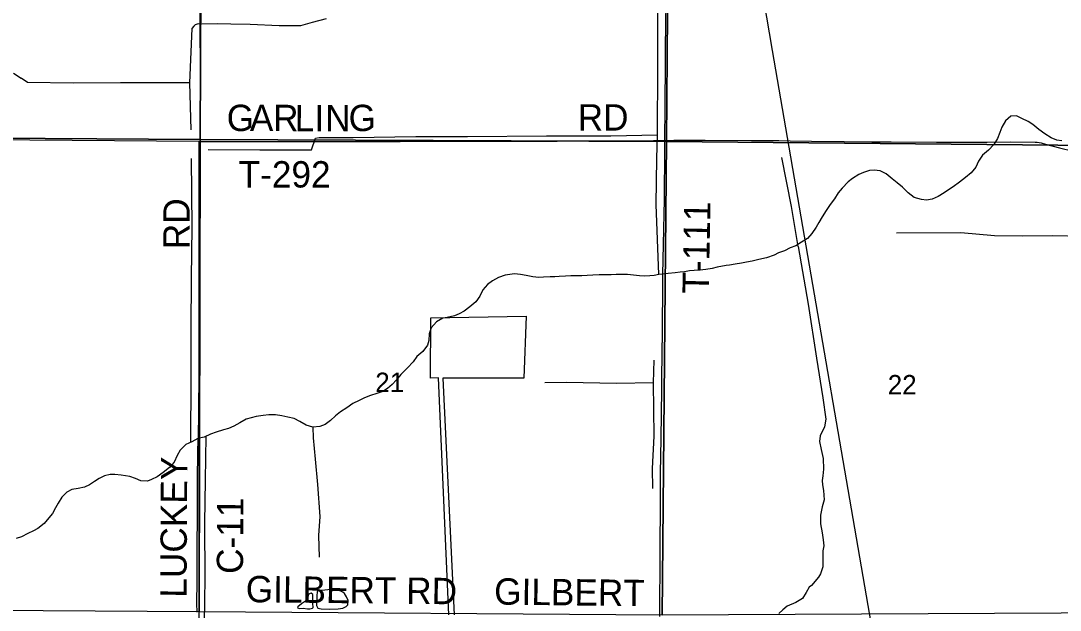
# Model space of a CAD drawing. Extents: x 1443599 to 1910620, y 1028088 to 1361369.
# Drawn here: x 1694297 to 1706140, y 1260936 to 1267645 of the extents above; entities that cross this region are included whole.
import ezdxf

# ---------------------------------------------------------------- set-up
doc = ezdxf.new("R2010")
doc.units = 0
for name, color, linetype in [('GM_X_Corporation', 7, 'Continuous'), ('GM_X_County_Road', 7, 'Continuous'), ('GM_X_County_Road_Text', 7, 'Continuous'), ('GM_X_Major_River', 7, 'Continuous'), ('GM_X_Minor_Lake', 7, 'Continuous'), ('GM_X_Minor_River', 7, 'Continuous'), ('GM_X_Rail_Line', 7, 'Continuous'), ('GM_X_Section', 7, 'Continuous'), ('GM_X_Section_Text', 7, 'Continuous'), ('GM_X_Township', 7, 'Continuous'), ('GM_X_Township_Road', 7, 'Continuous'), ('GM_X_Township_Road_Text', 7, 'Continuous')]:
    doc.layers.add(name, color=color, linetype=linetype)

msp = doc.modelspace()

# ---------------------------------------------------------------- linework, layer by layer
at = {"layer": 'GM_X_Corporation'}
msp.add_lwpolyline([(1699175, 1260884), (1699056, 1263580), (1698965, 1263578), (1698970, 1264262), (1700055, 1264281), (1700027, 1263577), (1699104, 1263575), (1699233, 1260884)], dxfattribs=at)
at = {"layer": 'GM_X_County_Road'}
for points in [[(1696343, 1266271), (1696343, 1266398), (1696343, 1266447), (1696343, 1266811), (1696343, 1267038), (1696343, 1267245), (1696342, 1267422), (1696341, 1267563), (1696340, 1267668), (1696339, 1267859), (1696339, 1268052), (1696337, 1268305), (1696338, 1268413), (1696337, 1268627), (1696337, 1268721), (1696336, 1268836), (1696337, 1268931)], [(1696305, 1260914), (1696304, 1261011), (1696305, 1261267), (1696306, 1261441), (1696307, 1261733), (1696310, 1261933), (1696311, 1262317), (1696311, 1262541), (1696313, 1262615), (1696315, 1262763), (1696321, 1262940), (1696325, 1263153), (1696327, 1263304), (1696329, 1263524), (1696329, 1263725), (1696331, 1263994), (1696331, 1264053), (1696331, 1264204), (1696331, 1264270), (1696335, 1264544), (1696335, 1264675), (1696336, 1264840), (1696336, 1264997), (1696338, 1265155), (1696338, 1265256), (1696338, 1265450), (1696339, 1265578), (1696339, 1265680), (1696341, 1266159), (1696343, 1266266), (1696343, 1266271)]]:
    msp.add_lwpolyline(points, dxfattribs=at)
at = {"layer": 'GM_X_Major_River'}
for points in [[(1705829, 1266464), (1705776, 1266497), (1705701, 1266533), (1705641, 1266562), (1705579, 1266560), (1705518, 1266507), (1705474, 1266434), (1705451, 1266372), (1705427, 1266303), (1705383, 1266238), (1705324, 1266173), (1705256, 1266115), (1705209, 1266046), (1705177, 1265980), (1705127, 1265915), (1705060, 1265861), (1704991, 1265808), (1704922, 1265754), (1704869, 1265721), (1704818, 1265688), (1704749, 1265644), (1704682, 1265616), (1704618, 1265603), (1704558, 1265611), (1704477, 1265633), (1704408, 1265688), (1704342, 1265750), (1704281, 1265802), (1704226, 1265847), (1704157, 1265901), (1704090, 1265936), (1704019, 1265946), (1703966, 1265941), (1703900, 1265919), (1703847, 1265894), (1703774, 1265850), (1703723, 1265811), (1703655, 1265741), (1703610, 1265686), (1703569, 1265620), (1703517, 1265552), (1703473, 1265487), (1703429, 1265415), (1703390, 1265348), (1703361, 1265297), (1703309, 1265224), (1703259, 1265165), (1703194, 1265123), (1703127, 1265084), (1703065, 1265060), (1702998, 1265027), (1702931, 1265005), (1702879, 1264978), (1702794, 1264948), (1702740, 1264936), (1702691, 1264922), (1702629, 1264910), (1702565, 1264897), (1702510, 1264885), (1702438, 1264874), (1702370, 1264864), (1702335, 1264858), (1702231, 1264839), (1702173, 1264827), (1702101, 1264814), (1702035, 1264806), (1701969, 1264802), (1701916, 1264797), (1701858, 1264788), (1701808, 1264783), (1701752, 1264777), (1701674, 1264767), (1701616, 1264760), (1701566, 1264757), (1701515, 1264744), (1701463, 1264742), (1701409, 1264739), (1701347, 1264742), (1701279, 1264750), (1701208, 1264756), (1701148, 1264757), (1701082, 1264755), (1701024, 1264752), (1700956, 1264752), (1700888, 1264754), (1700815, 1264749), (1700749, 1264745), (1700691, 1264740), (1700623, 1264742), (1700565, 1264741), (1700503, 1264737), (1700433, 1264733), (1700381, 1264732), (1700329, 1264729), (1700253, 1264725), (1700201, 1264722), (1700131, 1264732), (1700054, 1264744), (1699992, 1264755), (1699922, 1264763), (1699868, 1264756)], [(1706158, 1266279), (1706102, 1266285), (1706035, 1266314), (1705966, 1266358), (1705897, 1266406), (1705829, 1266464)], [(1699868, 1264756), (1699816, 1264751), (1699741, 1264723), (1699672, 1264683), (1699615, 1264642), (1699562, 1264583), (1699526, 1264512), (1699482, 1264445), (1699413, 1264390), (1699348, 1264340), (1699291, 1264311), (1699240, 1264286), (1699156, 1264266), (1699104, 1264258), (1699035, 1264217), (1698971, 1264151), (1698951, 1264081), (1698947, 1264007), (1698930, 1263954), (1698878, 1263882), (1698811, 1263822), (1698767, 1263763), (1698704, 1263694), (1698628, 1263620), (1698576, 1263557), (1698529, 1263504), (1698476, 1263459), (1698421, 1263425), (1698353, 1263402), (1698282, 1263378), (1698215, 1263353), (1698151, 1263323), (1698082, 1263287), (1698013, 1263240), (1697939, 1263192), (1697882, 1263147), (1697827, 1263094), (1697766, 1263048), (1697704, 1263026), (1697625, 1263021), (1697550, 1263043), (1697477, 1263083), (1697410, 1263116), (1697340, 1263134), (1697270, 1263148), (1697199, 1263158), (1697125, 1263159), (1697059, 1263151), (1696980, 1263139), (1696864, 1263110), (1696791, 1263067), (1696726, 1263031), (1696665, 1263004), (1696607, 1262990), (1696522, 1262962), (1696458, 1262941), (1696387, 1262907), (1696316, 1262890), (1696245, 1262854), (1696177, 1262820), (1696113, 1262759), (1696080, 1262698), (1696044, 1262622), (1695990, 1262560), (1695919, 1262503), (1695852, 1262455), (1695785, 1262424), (1695739, 1262404), (1695664, 1262407), (1695603, 1262433), (1695538, 1262458), (1695442, 1262473), (1695368, 1262480), (1695314, 1262480), (1695252, 1262465), (1695191, 1262433), (1695138, 1262402), (1695079, 1262361), (1695023, 1262337), (1694950, 1262322), (1694878, 1262310), (1694821, 1262279), (1694766, 1262221), (1694724, 1262155), (1694693, 1262102), (1694657, 1262037), (1694618, 1261986), (1694563, 1261921), (1694493, 1261866), (1694443, 1261838), (1694376, 1261807), (1694305, 1261769), (1694243, 1261750)]]:
    msp.add_lwpolyline(points, dxfattribs=at)
at = {"layer": 'GM_X_Minor_Lake'}
for p, q in [((1697625, 1261011), (1697626, 1261099)), ((1697670, 1261106), (1697667, 1260988))]:
    msp.add_line(p, q, dxfattribs=at)
for points in [[(1697667, 1260988), (1697680, 1260960), (1697718, 1260953), (1697818, 1260946), (1697912, 1260952), (1697966, 1260957), (1698004, 1260978), (1698023, 1260998), (1698028, 1261048), (1698009, 1261088), (1697986, 1261125), (1697967, 1261141), (1697909, 1261167), (1697829, 1261171), (1697763, 1261164), (1697717, 1261161), (1697677, 1261166), (1697670, 1261106)], [(1697626, 1261099), (1697624, 1261115), (1697604, 1261128), (1697576, 1261119), (1697565, 1261069), (1697540, 1261037), (1697495, 1261008), (1697454, 1260973), (1697448, 1260961), (1697468, 1260955), (1697514, 1260958), (1697562, 1260953), (1697592, 1260950), (1697622, 1260957), (1697630, 1260967), (1697625, 1261011)]]:
    msp.add_lwpolyline(points, dxfattribs=at)
at = {"layer": 'GM_X_Minor_River'}
for points in [[(1701566, 1264757), (1701537, 1265553), (1701545, 1266077), (1701551, 1266345), (1701554, 1267128), (1701557, 1267968)], [(1697777, 1267666), (1697616, 1267624), (1697483, 1267587), (1697241, 1267587), (1696909, 1267601), (1696689, 1267608), (1696543, 1267610), (1696359, 1267606), (1696317, 1267609), (1696285, 1267600), (1696267, 1267585), (1696246, 1267557), (1696221, 1266938), (1696235, 1266403)], [(1694214, 1267050), (1694300, 1266991)], [(1696221, 1266938), (1695433, 1266940), (1694893, 1266935), (1694373, 1266941), (1694300, 1266991)], [(1696432, 1266178), (1697020, 1266174), (1697608, 1266174), (1697655, 1266309), (1697697, 1266318), (1698085, 1266318), (1698799, 1266327), (1699387, 1266329), (1700287, 1266335), (1701021, 1266335), (1701551, 1266345)], [(1696233, 1262848), (1696237, 1263564), (1696237, 1264133), (1696242, 1264716), (1696248, 1265295), (1696241, 1266076)], [(1703153, 1265077), (1703078, 1265530), (1702970, 1266088)], [(1706393, 1265189), (1706055, 1265198), (1705709, 1265192), (1705392, 1265198), (1705009, 1265231), (1704275, 1265229)], [(1703153, 1265077), (1703267, 1264419), (1703362, 1263806), (1703434, 1263353), (1703468, 1263110), (1703454, 1263024), (1703405, 1262919), (1703398, 1262855), (1703416, 1262765), (1703439, 1262664), (1703442, 1262542), (1703434, 1262464), (1703429, 1262412), (1703430, 1262364), (1703444, 1262297), (1703451, 1262191), (1703427, 1262113), (1703409, 1262019), (1703409, 1261919), (1703426, 1261815), (1703440, 1261738), (1703448, 1261670), (1703435, 1261612), (1703435, 1261528), (1703434, 1261428), (1703407, 1261350), (1703386, 1261313), (1703305, 1261218), (1703279, 1261199), (1703245, 1261136), (1703204, 1261067), (1703128, 1261022), (1703029, 1260983), (1702978, 1260940), (1702935, 1260897)], [(1701509, 1263783), (1701503, 1263524), (1701508, 1262915), (1701489, 1262549), (1701493, 1262320)], [(1701503, 1263524), (1701087, 1263518), (1700511, 1263528), (1700269, 1263522)], [(1697625, 1263021), (1697628, 1262899), (1697650, 1262656), (1697677, 1262367), (1697704, 1262001), (1697689, 1261785), (1697695, 1261541)], [(1696405, 1262915), (1696396, 1262414), (1696392, 1261925), (1696393, 1261302), (1696388, 1260785), (1696388, 1259965), (1696359, 1259944), (1696369, 1259635), (1696390, 1259085), (1696387, 1258657), (1696362, 1258287), (1696373, 1258022), (1696362, 1257657), (1696353, 1257133)]]:
    msp.add_lwpolyline(points, dxfattribs=at)
at = {"layer": 'GM_X_Rail_Line'}
msp.add_lwpolyline([(1706691, 1244888), (1706606, 1245603), (1706377, 1246883), (1705814, 1250181), (1704887, 1255544), (1704203, 1259536), (1702861, 1267305), (1702177, 1271327), (1700946, 1278383), (1700946, 1278377), (1700041, 1283682), (1699417, 1287303)], dxfattribs=at)
at = {"layer": 'GM_X_Section'}
for points in [[(1691085, 1271702), (1696362, 1271606), (1696341, 1266293), (1691034, 1266328)], [(1701697, 1271615), (1701654, 1266271), (1696341, 1266293), (1696362, 1271606)], [(1706954, 1271617), (1706926, 1266222), (1701654, 1266271), (1701697, 1271615)], [(1696341, 1266293), (1696328, 1260919), (1690993, 1260950), (1691034, 1266328)], [(1701654, 1266271), (1701604, 1260880), (1696328, 1260919), (1696341, 1266293)], [(1706926, 1266222), (1706905, 1260906), (1701604, 1260880), (1701654, 1266271)]]:
    msp.add_lwpolyline(points, close=True, dxfattribs=at)
at = {"layer": 'GM_X_Township'}
for points in [[(1691028, 1266317), (1696325, 1266276), (1696324, 1260894), (1696308, 1259201), (1696305, 1258547), (1696301, 1258173), (1696288, 1257097), (1696269, 1255587), (1696154, 1250250)], [(1691028, 1266317), (1696325, 1266276), (1696324, 1260894), (1696308, 1259201), (1696305, 1258547), (1696301, 1258173), (1696288, 1257097), (1696269, 1255587), (1696154, 1250250), (1695980, 1244960), (1695885, 1241542), (1695846, 1239693), (1695686, 1234412), (1693554, 1234401)]]:
    msp.add_lwpolyline(points, dxfattribs=at)
at = {"layer": 'GM_X_Township_Road'}
for points in [[(1701635, 1266284), (1701636, 1266405), (1701639, 1266546), (1701640, 1266839), (1701642, 1267003), (1701643, 1267226), (1701644, 1267393), (1701646, 1267541), (1701646, 1267646), (1701650, 1267820), (1701652, 1268102), (1701653, 1268326), (1701653, 1268696), (1701654, 1268946), (1701654, 1268962)], [(1696343, 1266271), (1696387, 1266271), (1696754, 1266270), (1697125, 1266271)], [(1697125, 1266271), (1697208, 1266271), (1697462, 1266272), (1697800, 1266271), (1698184, 1266270), (1698358, 1266270), (1698621, 1266272), (1699921, 1266275), (1700193, 1266276), (1700407, 1266276), (1700646, 1266277), (1700942, 1266277), (1701165, 1266279), (1701356, 1266280), (1701507, 1266281), (1701635, 1266284)], [(1701580, 1260863), (1701579, 1261153), (1701581, 1261313), (1701582, 1261454), (1701582, 1261635), (1701583, 1261776), (1701585, 1262005), (1701586, 1262191), (1701587, 1262496), (1701593, 1262887), (1701600, 1263451), (1701602, 1263655), (1701604, 1263776), (1701608, 1264186), (1701612, 1264577), (1701613, 1264758), (1701620, 1265099), (1701628, 1265447), (1701630, 1265604), (1701632, 1265736), (1701635, 1266054), (1701634, 1266241), (1701635, 1266284)], [(1701635, 1266284), (1701648, 1266284), (1701736, 1266286), (1701904, 1266286), (1702094, 1266285), (1702623, 1266283), (1702935, 1266281), (1703062, 1266280), (1703308, 1266275), (1703679, 1266270), (1703994, 1266267), (1704214, 1266268), (1704730, 1266264), (1705203, 1266265), (1705308, 1266265), (1705570, 1266266), (1705853, 1266263), (1705877, 1266262), (1705899, 1266259), (1705922, 1266254), (1705974, 1266242), (1706133, 1266200), (1706287, 1266160)]]:
    msp.add_lwpolyline(points, dxfattribs=at)

# ---------------------------------------------------------------- texts
at = {"layer": 'GM_X_County_Road_Text'}
for s, rotation, p in [('RD', 90, (1696221, 1265045)), ('LUCKEY', 89.6626, (1696185, 1261077)), ('C-11', 89.6656, (1696829, 1261348))]:
    msp.add_text(s, height=300, rotation=rotation, dxfattribs=at).set_placement(p)
at = {"layer": 'GM_X_Section_Text'}
for s, p in [('21', (1698336, 1263419)), ('22', (1704175, 1263392))]:
    msp.add_text(s, height=221, rotation=0, dxfattribs=at).set_placement(p)
at = {"layer": 'GM_X_Township_Road_Text'}
for s, rotation, p in [('G', 359.8361, (1696643, 1266390)), ('A', 359.8347, (1696907, 1266390)), ('R', 359.8378, (1697171, 1266389)), ('L', 359.8329, (1697417, 1266388)), ('I', 359.8379, (1697642, 1266388)), ('N', 359.8667, (1697765, 1266387)), ('G', 0.7453, (1698034, 1266387)), ('RD', 0, (1700642, 1266395)), ('T-292', 0, (1696779, 1265747)), ('T-111', 88.8715, (1702135, 1264537)), ('GILBERT RD', 359.4123, (1696859, 1261027)), ('GILBERT', 359.3519, (1699689, 1261000))]:
    msp.add_text(s, height=300, rotation=rotation, dxfattribs=at).set_placement(p)

doc.saveas('drawing.dxf')
